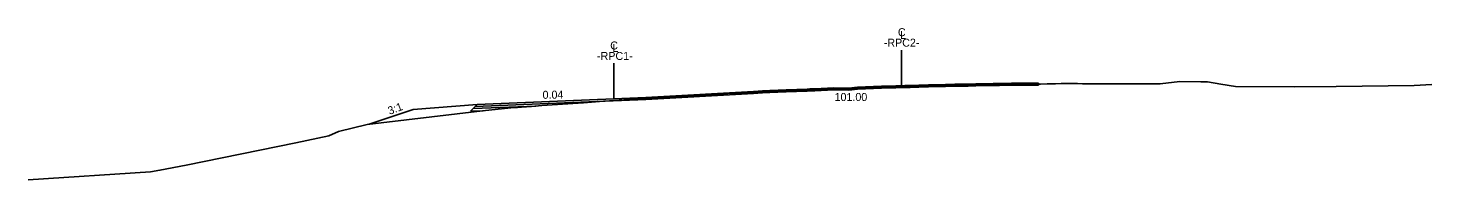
# Model space of a CAD drawing. Extents: x -313 to 385, y -480 to 1023.
# Drawn here: x -313.3 to -137.8, y 19.9 to 38.9 of the extents above; entities that cross this region are included whole.
import ezdxf

# ---------------------------------------------------------------- set-up
doc = ezdxf.new("R2010")
doc.units = 0
for name, color, linetype in [('Exist XS Center Line Elevation Label', 7, 'Continuous'), ('Exist XS Ground Line', 7, 'Continuous'), ('Prop CMT Pvmt Course 3 Wedge', 7, 'Continuous'), ('Prop CMT Pvmt Surface Overlay', 7, 'Continuous'), ('Prop CMT Shld Paved Course 1', 7, 'Continuous'), ('Prop CMT Shld Paved Course 2', 7, 'Continuous'), ('Prop CMT Slope Grass', 7, 'Continuous'), ('Prop XS Label Text', 7, 'Continuous'), ('Prop XS SE Text', 7, 'Continuous'), ('Prop XS Side Slope Text', 7, 'Continuous')]:
    doc.layers.add(name, color=color, linetype=linetype)

msp = doc.modelspace()

# ---------------------------------------------------------------- linework, layer by layer
at = {"layer": 'Exist XS Ground Line'}
msp.add_lwpolyline([(-313.26, 19.87), (-297.98, 20.9), (-296.79, 21.08), (-293.51, 21.71), (-279.78, 24.52), (-275.69, 25.38), (-274.46, 25.91), (-270.86, 26.82), (-269.12, 27.01), (-256.48, 28.51), (-252.91, 28.88), (-252.5, 28.91), (-252.09, 28.94), (-251.58, 28.98), (-250.34, 29.07), (-249.03, 29.18), (-247.1, 29.31), (-246.47, 29.35), (-243.86, 29.53), (-241.36, 29.7), (-240.61, 29.75), (-238.81, 29.87), (-237.37, 29.97), (-236.03, 30.06), (-234.51, 30.16), (-233.32, 30.23), (-231.13, 30.36), (-230.36, 30.39), (-229.85, 30.42), (-228.35, 30.49), (-227.39, 30.54), (-225.2, 30.7), (-224.62, 30.74), (-223.88, 30.77), (-223.5, 30.8), (-222.92, 30.8), (-221.47, 30.88), (-220.55, 30.92), (-218.5, 31), (-215.89, 31.11), (-215.54, 31.13), (-214.92, 31.15), (-212.57, 31.25), (-210.67, 31.23), (-209.61, 31.35), (-206.58, 31.45), (-204.81, 31.52), (-203.68, 31.55), (-203, 31.56), (-201.93, 31.59), (-200.72, 31.63), (-198.59, 31.69), (-197.41, 31.73), (-197.05, 31.73), (-196.52, 31.73), (-195.76, 31.73), (-194.79, 31.75), (-192.62, 31.8), (-191.83, 31.81), (-190.33, 31.83), (-188.86, 31.84), (-187.97, 31.85), (-186.7, 31.86), (-185.9, 31.87), (-184.86, 31.89), (-184.12, 31.91), (-182.58, 31.91), (-182.09, 31.91), (-181.49, 31.89), (-172.31, 31.9), (-171.77, 31.9), (-169.29, 32.17), (-166.69, 32.14), (-165.85, 32.13), (-164.19, 31.86), (-162.36, 31.56), (-154.96, 31.51), (-149.75, 31.57), (-140, 31.66), (-137.79, 31.79)], dxfattribs=at)
at = {"layer": 'Prop CMT Pvmt Course 3 Wedge'}
msp.add_line((-257.63, 28.81), (-257.98, 28.45), dxfattribs=at)
at = {"layer": 'Prop CMT Pvmt Surface Overlay'}
for p, q in [((-186.96, 31.73), (-186.96, 31.98)), ((-257.38, 29.06), (-236.03, 29.92)), ((-257.12, 29.32), (-236.03, 30.17)), ((-236.03, 30.17), (-222.59, 30.94)), ((-236.03, 29.92), (-222.59, 30.69))]:
    msp.add_line(p, q, dxfattribs=at)
for points in [[(-222.59, 30.94), (-221.47, 31), (-220.55, 31.04), (-218.5, 31.12), (-215.89, 31.24), (-215.54, 31.25), (-214.92, 31.28), (-212.57, 31.37), (-210.67, 31.36), (-209.61, 31.48), (-206.58, 31.58), (-204.81, 31.65), (-203.68, 31.67), (-203, 31.69), (-201.93, 31.72), (-200.72, 31.76), (-198.59, 31.82), (-197.41, 31.85), (-197.05, 31.85), (-196.52, 31.86), (-195.76, 31.86), (-194.79, 31.88), (-192.62, 31.93), (-191.83, 31.94), (-190.33, 31.95), (-188.86, 31.97), (-187.97, 31.97), (-186.96, 31.98)], [(-222.59, 30.69), (-221.47, 30.75), (-220.55, 30.79), (-218.5, 30.87), (-215.89, 30.99), (-215.54, 31), (-214.92, 31.03), (-212.57, 31.12), (-210.67, 31.11), (-209.61, 31.23), (-206.58, 31.33), (-204.81, 31.4), (-203.68, 31.42), (-203, 31.44), (-201.93, 31.47), (-200.72, 31.51), (-198.59, 31.57), (-197.41, 31.6), (-197.05, 31.6), (-196.52, 31.61), (-195.76, 31.61), (-194.79, 31.63), (-192.62, 31.68), (-191.83, 31.69), (-190.33, 31.7), (-188.86, 31.72), (-187.97, 31.72), (-186.96, 31.73)]]:
    msp.add_lwpolyline(points, dxfattribs=at)
at = {"layer": 'Prop CMT Shld Paved Course 1'}
msp.add_lwpolyline([(-257.12, 29.32), (-257.38, 29.06)], dxfattribs=at)
at = {"layer": 'Prop CMT Shld Paved Course 2'}
for p, q in [((-256.39, 28.52), (-257.98, 28.45)), ((-249.81, 29.11), (-257.64, 28.8))]:
    msp.add_line(p, q, dxfattribs=at)
msp.add_lwpolyline([(-257.37, 29.07), (-257.64, 28.8)], dxfattribs=at)
at = {"layer": 'Prop CMT Slope Grass'}
for p, q in [((-265.12, 28.68), (-270.63, 26.84)), ((-257.12, 29.32), (-265.12, 28.68))]:
    msp.add_line(p, q, dxfattribs=at)
at = {"layer": 'Prop XS Label Text'}
for p, q in [((-204.09, 31.66), (-204.09, 36.1)), ((-240.05, 30), (-240.05, 34.45))]:
    msp.add_line(p, q, dxfattribs=at)

# ---------------------------------------------------------------- texts
at = {"layer": 'Exist XS Center Line Elevation Label'}
msp.add_text('101.00', height=1, dxfattribs=at).set_placement((-212.46, 29.74))
at = {"layer": 'Prop XS Label Text'}
for s, p in [('C', (-204.54, 37.84)), ('C', (-240.5, 36.18)), ('L', (-240.22, 35.86)), ('-RPC2-', (-206.31, 36.53)), ('L', (-204.26, 37.51)), ('-RPC1-', (-242.15, 34.87))]:
    msp.add_text(s, height=1, dxfattribs=at).set_placement(p)
at = {"layer": 'Prop XS SE Text'}
msp.add_text('0.04', height=1, rotation=0.8783, dxfattribs=at).set_placement((-248.95, 30.01))
at = {"layer": 'Prop XS Side Slope Text'}
msp.add_text('3:1', height=1, rotation=20.6597, dxfattribs=at).set_placement((-268.08, 28))

doc.saveas('drawing.dxf')
